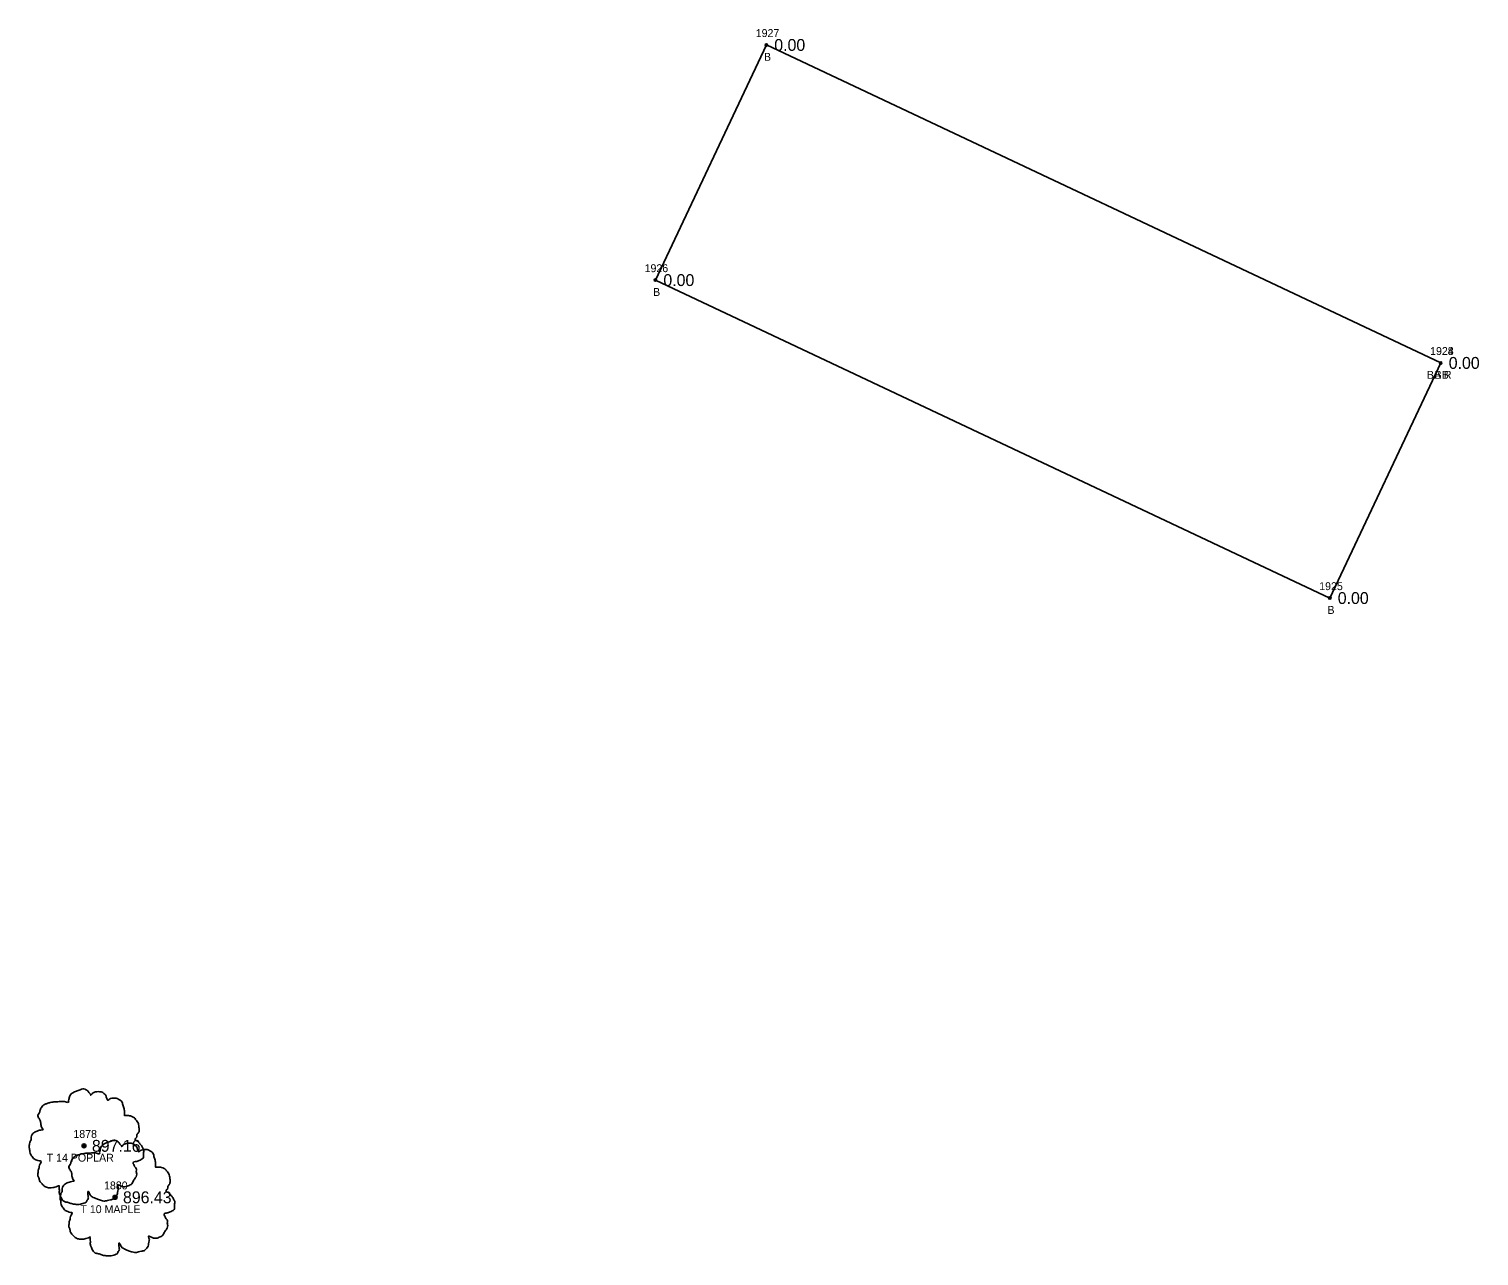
# Model space of a CAD drawing. Extents: x 1448136 to 1453623, y 1125056 to 1128842.
# Drawn here: x 1449762.1 to 1449945.2, y 1126858.2 to 1127013.1 of the extents above; entities that cross this region are included whole.
import ezdxf

# ---------------------------------------------------------------- set-up
doc = ezdxf.new("R2010")
doc.units = 0
for name, color, linetype in [('RD_EX_Bldg', 7, 'Continuous'), ('RD_EX_Bldg_txCode', 7, 'Continuous'), ('RD_EX_TX_Bldg_ELEV', 7, 'Continuous'), ('RD_EX_TX_VEG_ELEV', 7, 'Continuous'), ('RD_EX_VEG', 7, 'Continuous'), ('RD_EX_VEG_txCode', 7, 'Continuous'), ('RD_SMD_Locator', 7, 'Continuous')]:
    doc.layers.add(name, color=color, linetype=linetype)

msp = doc.modelspace()

# ---------------------------------------------------------------- linework, layer by layer
at = {"layer": 'RD_EX_Bldg'}
msp.add_lwpolyline([(1449940.34, 1126970.97), (1449926.33, 1126941.28), (1449841.2, 1126981.43), (1449855.2, 1127011.12), (1449940.34, 1126970.97)], dxfattribs=at)
at = {"layer": 'RD_EX_VEG'}
for centre, radius in [((1449769.06, 1126872.11), 0.25), ((1449769.05, 1126872.09), 0.0001), ((1449772.98, 1126865.61), 0.25), ((1449772.96, 1126865.6), 0.0001)]:
    msp.add_circle(centre, radius, dxfattribs=at)
for points in [[(1449769.2, 1126879.28), (1449768.9, 1126879.3), (1449768.57, 1126879.2), (1449768.32, 1126879.1), (1449768.1, 1126879.03), (1449767.87, 1126878.93), (1449767.57, 1126878.75), (1449767.35, 1126878.55), (1449767.22, 1126878.3), (1449767.17, 1126878.08), (1449767.12, 1126877.8), (1449767.12, 1126877.63), (1449767, 1126877.6), (1449766.85, 1126877.63), (1449766.6, 1126877.7), (1449766.35, 1126877.7), (1449766.1, 1126877.7), (1449765.75, 1126877.68), (1449765.4, 1126877.68), (1449765.12, 1126877.63), (1449764.8, 1126877.58), (1449764.42, 1126877.45), (1449764.07, 1126877.33), (1449763.77, 1126877.08), (1449763.52, 1126876.6), (1449763.4, 1126876.25), (1449763.25, 1126876), (1449763.4, 1126875.55), (1449763.57, 1126875.2), (1449763.6, 1126875), (1449763.67, 1126874.58), (1449763.77, 1126874.35), (1449763.9, 1126874.15), (1449763.82, 1126874.13), (1449763.45, 1126874.08), (1449763.15, 1126873.98), (1449762.72, 1126873.75), (1449762.5, 1126873.53), (1449762.4, 1126873.2), (1449762.37, 1126872.85), (1449762.27, 1126872.65), (1449762.2, 1126872.38), (1449762.17, 1126872.3), (1449762.12, 1126871.98), (1449762.22, 1126871.53), (1449762.25, 1126871.18), (1449762.37, 1126870.95), (1449762.52, 1126870.78), (1449762.7, 1126870.53), (1449763.1, 1126870.31), (1449763.42, 1126870.21), (1449763.62, 1126870.18), (1449763.45, 1126869.68), (1449763.4, 1126869.33), (1449763.27, 1126868.93), (1449763.27, 1126868.86), (1449763.22, 1126868.38), (1449763.37, 1126868.06), (1449763.45, 1126867.68), (1449763.62, 1126867.46), (1449763.9, 1126867.16), (1449764.22, 1126866.93), (1449764.72, 1126866.81), (1449765.12, 1126866.83), (1449765.7, 1126867.01), (1449765.95, 1126867.08), (1449765.92, 1126866.91), (1449765.95, 1126866.53), (1449765.95, 1126866.11), (1449766.1, 1126865.78), (1449766.2, 1126865.51), (1449766.35, 1126865.26), (1449766.67, 1126865.03), (1449767.07, 1126864.96), (1449767.5, 1126864.81), (1449767.95, 1126864.73), (1449768.45, 1126864.71), (1449769.05, 1126864.86), (1449769.32, 1126864.98), (1449769.42, 1126865.16), (1449769.62, 1126865.53), (1449769.57, 1126865.76), (1449769.6, 1126866.36), (1449769.7, 1126866.18), (1449769.87, 1126865.83), (1449770.37, 1126865.53), (1449770.77, 1126865.36), (1449771.25, 1126865.21), (1449771.55, 1126865.13), (1449772.02, 1126865.21), (1449772.4, 1126865.28), (1449772.77, 1126865.41), (1449773.07, 1126865.68), (1449773.24, 1126865.96), (1449773.29, 1126866.23), (1449773.37, 1126866.61), (1449773.42, 1126866.78)], [(1449773.42, 1126866.78), (1449773.34, 1126866.96), (1449773.29, 1126867.21), (1449773.37, 1126867.18), (1449773.54, 1126867.13), (1449773.82, 1126867.01), (1449774.04, 1126866.93), (1449774.37, 1126866.96), (1449774.64, 1126867.06), (1449775.09, 1126867.33), (1449775.37, 1126867.81), (1449775.64, 1126868.21), (1449775.72, 1126868.53), (1449775.67, 1126868.76), (1449775.64, 1126869.26), (1449775.44, 1126869.51), (1449775.39, 1126869.63), (1449775.29, 1126870.03), (1449775.37, 1126870.08), (1449775.64, 1126870.13), (1449776.02, 1126870.26), (1449776.29, 1126870.38), (1449776.52, 1126870.56), (1449776.59, 1126870.78), (1449776.57, 1126871.18), (1449776.62, 1126871.58), (1449776.54, 1126871.73), (1449776.44, 1126871.88), (1449776.37, 1126872.08), (1449776.22, 1126872.23), (1449776.12, 1126872.38), (1449776.02, 1126872.48), (1449775.89, 1126872.63), (1449775.72, 1126872.75), (1449775.57, 1126872.8), (1449775.52, 1126872.95), (1449775.67, 1126873.15), (1449775.72, 1126873.25), (1449775.74, 1126873.48), (1449775.97, 1126873.83), (1449776.02, 1126874.23), (1449775.97, 1126874.65), (1449775.92, 1126874.93), (1449775.77, 1126875.2), (1449775.57, 1126875.45), (1449775.44, 1126875.63), (1449775.27, 1126875.75), (1449774.94, 1126875.88), (1449774.69, 1126875.93), (1449774.34, 1126875.93), (1449774.14, 1126875.98), (1449774.17, 1126876.03), (1449774.17, 1126876.18), (1449774.17, 1126876.45), (1449774.09, 1126876.9), (1449773.94, 1126877.4), (1449773.94, 1126877.43), (1449773.84, 1126877.68), (1449773.62, 1126877.88), (1449773.44, 1126877.98), (1449773.24, 1126878.1), (1449772.99, 1126878.13), (1449772.7, 1126878.13), (1449772.42, 1126878.08), (1449772.22, 1126877.98), (1449772.05, 1126877.85), (1449771.97, 1126878), (1449771.87, 1126878.3), (1449771.82, 1126878.45), (1449771.67, 1126878.63), (1449771.45, 1126878.83), (1449771, 1126878.95), (1449770.37, 1126878.88), (1449770.07, 1126878.68), (1449769.92, 1126878.5), (1449769.87, 1126878.63), (1449769.67, 1126878.83), (1449769.57, 1126879), (1449769.4, 1126879.13), (1449769.25, 1126879.23), (1449769.15, 1126879.28)], [(1449773.11, 1126872.78), (1449772.81, 1126872.81), (1449772.48, 1126872.71), (1449772.23, 1126872.61), (1449772.01, 1126872.53), (1449771.78, 1126872.43), (1449771.48, 1126872.26), (1449771.26, 1126872.06), (1449771.13, 1126871.81), (1449771.08, 1126871.58), (1449771.03, 1126871.31), (1449771.03, 1126871.13), (1449770.91, 1126871.11), (1449770.76, 1126871.13), (1449770.51, 1126871.21), (1449770.26, 1126871.21), (1449770.01, 1126871.21), (1449769.66, 1126871.18), (1449769.31, 1126871.18), (1449769.03, 1126871.13), (1449768.71, 1126871.08), (1449768.33, 1126870.96), (1449767.98, 1126870.83), (1449767.69, 1126870.58), (1449767.44, 1126870.11), (1449767.31, 1126869.76), (1449767.16, 1126869.51), (1449767.31, 1126869.06), (1449767.49, 1126868.71), (1449767.51, 1126868.51), (1449767.59, 1126868.08), (1449767.69, 1126867.86), (1449767.81, 1126867.66), (1449767.74, 1126867.63), (1449767.36, 1126867.58), (1449767.06, 1126867.48), (1449766.64, 1126867.26), (1449766.41, 1126867.03), (1449766.31, 1126866.71), (1449766.29, 1126866.36), (1449766.19, 1126866.16), (1449766.11, 1126865.89), (1449766.09, 1126865.81), (1449766.04, 1126865.49), (1449766.14, 1126865.04), (1449766.16, 1126864.69), (1449766.29, 1126864.46), (1449766.44, 1126864.29), (1449766.61, 1126864.04), (1449767.01, 1126863.81), (1449767.34, 1126863.71), (1449767.54, 1126863.69), (1449767.36, 1126863.19), (1449767.31, 1126862.84), (1449767.19, 1126862.44), (1449767.19, 1126862.36), (1449767.14, 1126861.89), (1449767.29, 1126861.56), (1449767.36, 1126861.19), (1449767.54, 1126860.96), (1449767.81, 1126860.66), (1449768.13, 1126860.44), (1449768.63, 1126860.31), (1449769.03, 1126860.34), (1449769.61, 1126860.51), (1449769.86, 1126860.59), (1449769.83, 1126860.41), (1449769.86, 1126860.04), (1449769.86, 1126859.61), (1449770.01, 1126859.29), (1449770.11, 1126859.01), (1449770.26, 1126858.76), (1449770.58, 1126858.54), (1449770.98, 1126858.46), (1449771.41, 1126858.31), (1449771.86, 1126858.24), (1449772.36, 1126858.21), (1449772.96, 1126858.36), (1449773.23, 1126858.49), (1449773.33, 1126858.66), (1449773.53, 1126859.04), (1449773.48, 1126859.26), (1449773.51, 1126859.86), (1449773.61, 1126859.69), (1449773.78, 1126859.34), (1449774.28, 1126859.04), (1449774.68, 1126858.86), (1449775.16, 1126858.71), (1449775.46, 1126858.64), (1449775.93, 1126858.71), (1449776.31, 1126858.79), (1449776.68, 1126858.91), (1449776.98, 1126859.19), (1449777.16, 1126859.46), (1449777.21, 1126859.74), (1449777.28, 1126860.11), (1449777.33, 1126860.29)], [(1449777.33, 1126860.29), (1449777.26, 1126860.46), (1449777.21, 1126860.71), (1449777.28, 1126860.69), (1449777.46, 1126860.64), (1449777.73, 1126860.51), (1449777.96, 1126860.44), (1449778.28, 1126860.46), (1449778.56, 1126860.56), (1449779.01, 1126860.84), (1449779.28, 1126861.31), (1449779.55, 1126861.71), (1449779.63, 1126862.04), (1449779.58, 1126862.26), (1449779.55, 1126862.76), (1449779.35, 1126863.01), (1449779.3, 1126863.14), (1449779.2, 1126863.54), (1449779.28, 1126863.59), (1449779.55, 1126863.64), (1449779.93, 1126863.76), (1449780.2, 1126863.89), (1449780.43, 1126864.06), (1449780.5, 1126864.29), (1449780.48, 1126864.69), (1449780.53, 1126865.09), (1449780.45, 1126865.24), (1449780.35, 1126865.39), (1449780.28, 1126865.59), (1449780.13, 1126865.74), (1449780.03, 1126865.89), (1449779.93, 1126865.99), (1449779.8, 1126866.14), (1449779.63, 1126866.26), (1449779.48, 1126866.31), (1449779.43, 1126866.46), (1449779.58, 1126866.66), (1449779.63, 1126866.76), (1449779.65, 1126866.98), (1449779.88, 1126867.33), (1449779.93, 1126867.73), (1449779.88, 1126868.16), (1449779.83, 1126868.43), (1449779.68, 1126868.71), (1449779.48, 1126868.96), (1449779.35, 1126869.13), (1449779.18, 1126869.26), (1449778.86, 1126869.38), (1449778.61, 1126869.43), (1449778.26, 1126869.43), (1449778.06, 1126869.48), (1449778.08, 1126869.53), (1449778.08, 1126869.68), (1449778.08, 1126869.96), (1449778.01, 1126870.41), (1449777.86, 1126870.91), (1449777.86, 1126870.93), (1449777.76, 1126871.18), (1449777.53, 1126871.38), (1449777.36, 1126871.48), (1449777.16, 1126871.61), (1449776.91, 1126871.63), (1449776.61, 1126871.63), (1449776.33, 1126871.58), (1449776.13, 1126871.48), (1449775.96, 1126871.36), (1449775.88, 1126871.51), (1449775.78, 1126871.81), (1449775.73, 1126871.96), (1449775.58, 1126872.13), (1449775.36, 1126872.33), (1449774.91, 1126872.46), (1449774.28, 1126872.38), (1449773.98, 1126872.18), (1449773.83, 1126872.01), (1449773.78, 1126872.13), (1449773.58, 1126872.33), (1449773.48, 1126872.51), (1449773.31, 1126872.63), (1449773.16, 1126872.73), (1449773.06, 1126872.78)]]:
    msp.add_spline(points, degree=3, dxfattribs=at)
at = {"layer": 'RD_SMD_Locator'}
for centre in [(1449855.2, 1127011.12), (1449841.2, 1126981.43), (1449940.34, 1126970.97), (1449940.34, 1126970.97), (1449926.33, 1126941.28), (1449769.06, 1126872.11), (1449772.98, 1126865.61)]:
    msp.add_circle(centre, 0.15, dxfattribs=at)

# ---------------------------------------------------------------- texts
at = {"layer": 'RD_EX_Bldg_txCode'}
for s, p in [('1927', (1449853.86, 1127012.12)), ('B', (1449854.9, 1127009.12)), ('1926', (1449839.83, 1126982.43)), ('B', (1449840.9, 1126979.43)), ('1924', (1449938.99, 1126971.97)), ('1928', (1449938.99, 1126971.97)), ('BA R', (1449938.58, 1126968.97)), ('BB', (1449939.56, 1126968.97)), ('1925', (1449924.99, 1126942.28)), ('B', (1449926.03, 1126939.28))]:
    msp.add_text(s, height=1, dxfattribs=at).set_placement(p)
at = {"layer": 'RD_EX_TX_Bldg_ELEV'}
for p in [(1449856.2, 1127010.37), (1449842.2, 1126980.68), (1449941.34, 1126970.22), (1449941.34, 1126970.22), (1449927.33, 1126940.53)]:
    msp.add_text('0.00', height=1.5, dxfattribs=at).set_placement(p)
at = {"layer": 'RD_EX_TX_VEG_ELEV'}
for s, p in [('897.16', (1449770.06, 1126871.36)), ('896.43', (1449773.98, 1126864.86))]:
    msp.add_text(s, height=1.5, dxfattribs=at).set_placement(p)
at = {"layer": 'RD_EX_VEG_txCode'}
for s, p in [('1878', (1449767.72, 1126873.11)), ('T 14 POPLAR', (1449764.35, 1126870.11)), ('1880', (1449771.59, 1126866.61)), ('T 10 MAPLE', (1449768.61, 1126863.61))]:
    msp.add_text(s, height=1, dxfattribs=at).set_placement(p)

doc.saveas('drawing.dxf')
